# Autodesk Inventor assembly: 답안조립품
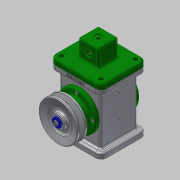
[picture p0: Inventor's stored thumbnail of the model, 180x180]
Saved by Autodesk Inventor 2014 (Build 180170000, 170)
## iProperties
Created: 2017-08
Part Number: 답안조립품
Document SubType Name: Assembly
Designer: 601-04
Author: 601-04
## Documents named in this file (18)
- C:\Users\601-04\Desktop\470808V1009\답안조립품.iam
- C:\Users\601-04\Desktop\470808V1009\1-본체.ipt
- C:\Users\601-04\Desktop\470808V1009\E-링.ipt
- C:\Users\601-04\Desktop\470808V1009\V-벨트풀리.ipt
- C:\Users\601-04\Desktop\470808V1009\덮개.ipt
- C:\Users\601-04\Desktop\470808V1009\뒤커버.ipt
- C:\Users\601-04\Desktop\470808V1009\링크.ipt
- C:\Users\601-04\Desktop\470808V1009\베어링 17 x 40 x 12.ipt
- C:\Users\601-04\Desktop\470808V1009\볼트 M4 x 8.ipt
- C:\Users\601-04\Desktop\470808V1009\볼트 M4 x 10.ipt
- C:\Users\601-04\Desktop\470808V1009\슬라이더.ipt
- C:\Users\601-04\Desktop\470808V1009\앞커버.ipt
- C:\Users\601-04\Desktop\470808V1009\오일 실 17 30 8.ipt
- C:\Users\601-04\Desktop\470808V1009\와셔 4x16.ipt
- C:\Users\601-04\Desktop\470808V1009\클레비스 핀 6 x 22.ipt
- 클레비스 핀 6 x 22.ipt
- C:\Users\601-04\Desktop\470808V1009\키 4 x 4 x 12.ipt
- C:\Users\601-04\Desktop\470808V1009\편심축.ipt
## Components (3 placed, 3 different names)
1. 1-본체:1
2. E-링:1
3. V-벨트풀리:1
